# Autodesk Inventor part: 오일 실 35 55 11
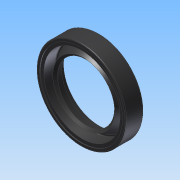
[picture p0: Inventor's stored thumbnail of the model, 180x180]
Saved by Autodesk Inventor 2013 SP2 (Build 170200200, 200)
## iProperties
Created: 2025-06
Part Number: 오일 실 35 55 11
Material: Generic
Document SubType Name: Modeling
Designer: a
Density: 1 g/cm^3
Author: a
변환 표준: STEP AP214IS
전처리기: Build: 200, Release: 2013 SP2 Update 6 - Date: Thu 07/17/2014
전송 단위: 밀리미터
불확실성: 0.01
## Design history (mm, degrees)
node "오일 실 35 55 111"
body "Solid1"
node "기준1"
